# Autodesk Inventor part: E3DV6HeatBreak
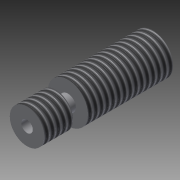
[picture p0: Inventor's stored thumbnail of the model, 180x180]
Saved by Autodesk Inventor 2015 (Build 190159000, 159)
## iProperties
Created: 2014-08
Part Number: E3DV6HeatBreak
Material: Generic
Document SubType Name: Modeling
Designer: Jack
Density: 1 g/cm^3
Appearance: Default
Author: Jack
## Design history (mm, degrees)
sketch "Sketch1"
  geometry: L1 (0, 0)-(3, 0); L2 (3, 0)-(3, 5); L3 (3, 5)-(1.4, 5); L4 (1.4, 5)-(1.4, 7.1); L5 (1.4, 7.1)-(3.5, 7.1); L6 (3.5, 7.1)-(3.5, 21.9); L7 (3.5, 21.9)-(0, 21.9); L8 (0, 21.9)-(0, 0)
  constraints: 16 end point, 5 perpendicular, 2 vertical, 1 horizontal
  dimensions: "d0" = 3 distance of L1.start L1.end; "d1" = 5 distance of L1.end L2.end; "d2" = 1.4 horizontal distance of L1.start L3.end; "d3" = 2.1 distance of L3.end L4.end; "d4" = 3.5 horizontal distance of L1.start L5.end; "d5" = 14.8 distance of L5.end L6.end
revolve "Revolution1" sketch "Sketch1" stored, may be unused: angle "d6" = 90 deg
thread "Thread1" dims "d7" = 10, "d8" = 0
thread "Thread2" dims "d9" = 10, "d10" = 0
sketch "Sketch2"
  geometry: C1 r 3.5 at (0, 0) reference; C2 r 1 at (0, 0)
  constraints: 1 centre point, 1 coincident
  dimensions: "d11" = 2 diameter of C2
extrude "Extrusion1" cut sketch "Sketch2" stored distance "d12" = 10; taper "d13" = 0 deg
sketch "Sketch3"
  geometry: C1 r 1 at (0, 0) reference; C2 r 3.5 at (0, 0) reference; C3 r 2.1 at (0, 0)
  constraints: 1 centre point, 1 coincident
  dimensions: "d14" = 4.2 diameter of C3
extrude "Extrusion2" cut sketch "Sketch3" distance "d15" = 10.5; taper "d16" = 0 deg
body "Solid1"
